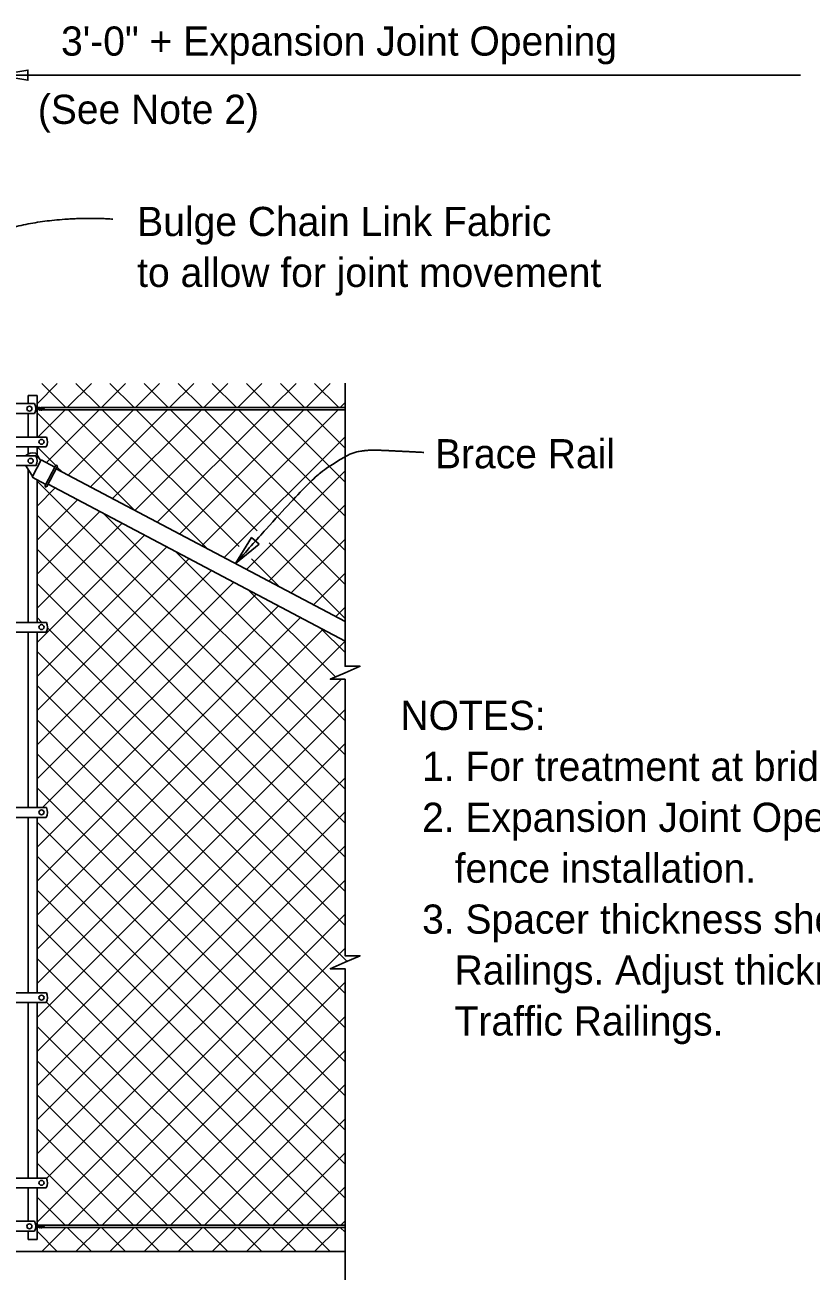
# Model space of a CAD drawing. Extents: x 0.5 to 39.7, y 0.9 to 25.6.
# Drawn here: x 28.76 to 34.2, y 17 to 25.61 of the extents above; entities that cross this region are included whole.
import ezdxf

# ---------------------------------------------------------------- set-up
doc = ezdxf.new("R2010")
doc.units = 0
for name, color, linetype in [('Dimension', 7, 'Continuous'), ('Miscellaneous', 7, 'Continuous'), ('SteelMisc', 7, 'Continuous'), ('SupstrConc', 7, 'Continuous'), ('TextStructures', 7, 'Continuous')]:
    doc.layers.add(name, color=color, linetype=linetype)

msp = doc.modelspace()

# ---------------------------------------------------------------- linework, layer by layer
at = {"layer": 'Dimension'}
msp.add_line((25.6609, 25.2672), (34.1233, 25.2672), dxfattribs=at)
for points in [[(28.5762, 25.2672), (28.7845, 25.2319), (28.7845, 25.3025)], [(30.3825, 22.0243), (30.2184, 21.8914), (30.3296, 22.071)]]:
    msp.add_lwpolyline(points, close=True, dxfattribs=at)
for points in [[(30.9762, 23.1382), (30.9762, 21.1819), (31.0795, 21.1819), (30.9762, 21.1369), (30.8729, 21.0919), (30.9762, 21.0919), (30.9762, 20.1983)], [(30.9762, 20.1983), (30.9762, 19.1806), (31.0795, 19.1806), (30.9762, 19.1356), (30.8729, 19.0906), (30.9762, 19.0906), (30.9762, 17.1361)], [(30.9761, 17.1361), (30.9761, 15.7022), (31.0795, 15.7022), (30.9761, 15.6572), (30.8728, 15.6122), (30.9761, 15.6122), (30.9761, 13.3448)]]:
    msp.add_lwpolyline(points, dxfattribs=at)
for points in [[(29.3712, 24.2725), (28.9427, 24.2977), (28.2117, 24.0791), (27.9092, 23.4903), (27.7412, 21.9834)], [(31.5199, 22.6596), (31.3633, 22.6678), (31.0749, 22.6809), (30.9256, 22.6043), (30.718, 22.4586), (30.2184, 21.8914)]]:
    msp.add_open_spline(points, degree=2, dxfattribs=at)
at = {"layer": 'Miscellaneous'}
for p, q in [((28.8471, 22.996), (28.9872, 23.1361)), ((28.8798, 23.1361), (29.0465, 22.9695)), ((29.0563, 22.9695), (29.2229, 23.1361)), ((29.1155, 23.1361), (29.2822, 22.9695)), ((29.292, 22.9695), (29.4586, 23.1361)), ((29.3512, 23.1361), (29.5179, 22.9695)), ((29.5277, 22.9695), (29.6943, 23.1361)), ((29.5869, 23.1361), (29.7536, 22.9695)), ((29.7634, 22.9695), (29.9301, 23.1361)), ((29.8226, 23.1361), (29.9893, 22.9695)), ((29.9991, 22.9695), (30.1658, 23.1361)), ((30.0583, 23.1361), (30.225, 22.9695)), ((30.2348, 22.9695), (30.4015, 23.1361)), ((30.294, 23.1361), (30.4607, 22.9695)), ((30.4705, 22.9695), (30.6372, 23.1361)), ((30.5297, 23.1361), (30.6964, 22.9695)), ((30.7062, 22.9695), (30.8729, 23.1361)), ((30.7654, 23.1361), (30.9321, 22.9695)), ((30.9419, 22.9695), (30.9762, 23.0038)), ((28.8471, 22.9331), (29.5195, 22.2607)), ((28.8522, 22.7654), (29.0415, 22.9547)), ((28.912, 22.5894), (29.2772, 22.9547)), ((29.0612, 22.9547), (30.0194, 21.9966)), ((29.0612, 22.5029), (29.5129, 22.9547)), ((29.2154, 22.4214), (29.7486, 22.9547)), ((29.2969, 22.9547), (30.2432, 22.0084)), ((29.3696, 22.3399), (29.9843, 22.9547)), ((29.5238, 22.2584), (30.22, 22.9547)), ((29.5326, 22.9547), (30.3688, 22.1185)), ((29.678, 22.177), (30.4557, 22.9547)), ((29.7683, 22.9547), (30.9762, 21.7468)), ((29.8322, 22.0955), (30.6914, 22.9547)), ((29.9864, 22.014), (30.9271, 22.9547)), ((30.004, 22.9547), (30.9762, 21.9825)), ((30.2397, 22.9547), (30.9762, 22.2182)), ((30.4754, 22.9547), (30.9762, 22.4539)), ((30.7111, 22.9547), (30.9762, 22.6896)), ((30.1406, 21.9325), (30.9762, 22.768)), ((28.8471, 22.6974), (28.9759, 22.5686)), ((28.9859, 22.5586), (29.0197, 22.5249)), ((30.2948, 21.851), (30.9762, 22.5323)), ((28.8471, 22.4617), (30.9762, 20.3326)), ((28.8471, 22.2889), (28.9724, 22.4142)), ((28.8471, 22.0532), (29.1266, 22.3327)), ((28.8471, 21.8175), (29.2808, 22.2512)), ((28.8471, 22.226), (30.9762, 20.0969)), ((29.3074, 22.2372), (30.9762, 20.5683)), ((30.449, 21.7695), (30.9762, 22.2966)), ((28.8471, 21.5818), (29.435, 22.1697)), ((28.8471, 21.3461), (29.5892, 22.0882)), ((30.6032, 21.688), (30.9762, 22.0609)), ((28.8471, 21.1104), (29.7434, 22.0067)), ((28.8471, 21.9903), (30.9762, 19.8612)), ((29.8072, 21.973), (30.9762, 20.804)), ((30.4517, 22.0356), (30.9762, 21.5111)), ((28.8471, 20.8747), (29.8977, 21.9252)), ((30.3281, 21.9235), (30.5192, 21.7324)), ((28.8471, 20.639), (30.0519, 21.8437)), ((30.7575, 21.6065), (30.9762, 21.8252)), ((28.8471, 20.4033), (30.2061, 21.7622)), ((28.8471, 21.7546), (30.9762, 19.6255)), ((30.307, 21.7089), (30.9085, 21.1074)), ((28.8897, 20.2102), (30.3603, 21.6807)), ((28.8471, 19.9319), (30.5145, 21.5993)), ((30.9117, 21.525), (30.9762, 21.5895)), ((28.8471, 21.5189), (28.8812, 21.4848)), ((28.8471, 19.6962), (30.6687, 21.5178)), ((28.8471, 19.4605), (30.8229, 21.4363)), ((28.9195, 21.4465), (30.9762, 19.3898)), ((30.8069, 21.4448), (30.9762, 21.2754)), ((28.8471, 19.2248), (30.9762, 21.3538)), ((28.8471, 21.2832), (30.9891, 19.1412)), ((28.8471, 18.9891), (30.95, 21.0919)), ((28.8471, 21.0475), (30.9762, 18.9184)), ((28.8471, 18.7534), (30.9762, 20.8824)), ((28.8471, 20.8118), (30.9762, 18.6827)), ((28.8471, 18.5177), (30.9762, 20.6467)), ((28.8471, 20.5761), (30.9762, 18.447)), ((28.8471, 18.282), (30.9762, 20.411)), ((28.8471, 20.3404), (30.9762, 18.2113)), ((28.8471, 18.0462), (30.9762, 20.1753)), ((28.8471, 20.1047), (30.9762, 17.9756)), ((28.8471, 17.8105), (30.9762, 19.9396)), ((28.8471, 19.869), (30.9762, 17.7399)), ((28.9129, 17.6406), (30.9762, 19.7039)), ((28.8471, 19.6333), (30.9762, 17.5042)), ((28.8471, 17.3391), (30.9762, 19.4682)), ((28.8471, 19.3976), (30.9271, 17.3175)), ((29.0612, 17.3175), (30.9762, 19.2325)), ((28.8471, 19.1619), (30.6914, 17.3175)), ((29.2969, 17.3175), (30.9762, 18.9968)), ((28.9129, 18.8604), (30.4557, 17.3175)), ((29.5326, 17.3175), (30.9762, 18.7611)), ((28.8471, 18.6905), (30.22, 17.3175)), ((29.7683, 17.3175), (30.9762, 18.5254)), ((28.8471, 18.4548), (29.9843, 17.3175)), ((30.004, 17.3175), (30.9762, 18.2897)), ((28.8471, 18.219), (29.7486, 17.3175)), ((30.2397, 17.3175), (30.9762, 18.054)), ((28.8471, 17.9833), (29.5129, 17.3175)), ((28.8471, 17.7476), (29.2772, 17.3175)), ((30.4754, 17.3175), (30.9762, 17.8183)), ((30.7111, 17.3175), (30.9762, 17.5826)), ((28.8471, 17.5119), (29.0415, 17.3175)), ((30.9468, 17.3175), (30.9762, 17.3469)), ((28.8471, 17.2762), (28.9872, 17.1361)), ((28.8798, 17.1361), (29.0465, 17.3028)), ((29.0563, 17.3028), (29.2229, 17.1361)), ((29.1155, 17.1361), (29.2822, 17.3028)), ((29.292, 17.3028), (29.4586, 17.1361)), ((29.3512, 17.1361), (29.5179, 17.3028)), ((29.5277, 17.3028), (29.6943, 17.1361)), ((29.5869, 17.1361), (29.7536, 17.3028)), ((29.7634, 17.3028), (29.9301, 17.1361)), ((29.8226, 17.1361), (29.9893, 17.3028)), ((29.9991, 17.3028), (30.1658, 17.1361)), ((30.0583, 17.1361), (30.225, 17.3028)), ((30.2348, 17.3028), (30.4015, 17.1361)), ((30.294, 17.1361), (30.4607, 17.3028)), ((30.4705, 17.3028), (30.6372, 17.1361)), ((30.5297, 17.1361), (30.6964, 17.3028)), ((30.7062, 17.3028), (30.8729, 17.1361)), ((30.7654, 17.1361), (30.9321, 17.3028)), ((30.9419, 17.3028), (30.9762, 17.2685))]:
    msp.add_line(p, q, dxfattribs=at)
at = {"layer": 'SteelMisc'}
for p, q in [((28.7846, 22.9966), (28.7846, 23.0528)), ((28.7846, 23.0528), (28.8471, 23.0528)), ((28.7846, 22.9966), (28.7846, 23.0528)), ((28.7846, 23.0528), (28.8471, 23.0528)), ((28.8471, 22.9726), (28.8471, 23.0528)), ((28.8471, 22.9726), (28.8471, 23.0528)), ((28.4206, 22.9966), (28.8303, 22.9966)), ((28.4206, 22.9289), (28.8299, 22.9289)), ((28.7846, 22.9288), (28.7846, 22.7653)), ((28.7846, 22.9288), (28.7846, 22.7653)), ((28.8376, 22.9741), (28.8668, 22.9695)), ((28.8377, 22.9741), (28.8669, 22.9695)), ((28.8381, 22.9537), (28.8717, 22.9593)), ((28.8382, 22.9691), (28.8642, 22.965)), ((28.8382, 22.9537), (28.8718, 22.9593)), ((28.8383, 22.9691), (28.8643, 22.965)), ((28.8385, 22.9585), (28.8684, 22.9634)), ((28.8386, 22.9585), (28.8685, 22.9634)), ((28.8471, 22.9676), (28.8471, 22.9598)), ((28.8471, 22.9676), (28.8471, 22.9598)), ((28.8471, 22.9552), (28.8471, 22.7653)), ((28.8471, 22.9552), (28.8471, 22.7653)), ((28.8842, 22.9547), (30.9762, 22.9547)), ((28.8855, 22.9695), (30.9762, 22.9695)), ((28.4206, 22.7654), (28.9116, 22.7654)), ((28.4206, 22.6977), (28.9109, 22.6977)), ((28.7846, 22.6487), (28.7846, 22.6977)), ((28.8471, 22.6411), (28.8471, 22.6977)), ((28.3139, 22.6358), (28.8387, 22.6358)), ((28.8763, 22.6083), (28.8126, 22.4877)), ((28.8728, 22.6018), (28.8381, 22.6549)), ((28.8763, 22.6083), (28.9706, 22.5585)), ((28.3139, 22.568), (28.8387, 22.568)), ((28.8168, 22.4958), (28.7699, 22.5675)), ((28.7846, 21.4848), (28.7846, 22.545)), ((28.9069, 22.4379), (28.8126, 22.4877)), ((28.9752, 22.5671), (28.9027, 22.43)), ((28.987, 22.5609), (28.9146, 22.4237)), ((30.9762, 21.4909), (28.9793, 22.5462)), ((28.8471, 21.4848), (28.8471, 22.4695)), ((30.9762, 21.3553), (28.9232, 22.4401)), ((28.4206, 21.4848), (28.9116, 21.4848)), ((28.4206, 21.4172), (28.9109, 21.4172)), ((28.7846, 20.2043), (28.7846, 21.4172)), ((28.8471, 20.2043), (28.8471, 21.4172)), ((28.4206, 20.2043), (28.9116, 20.2043)), ((28.4206, 20.1367), (28.9109, 20.1367)), ((28.7846, 18.9238), (28.7846, 20.1367)), ((28.8471, 18.9238), (28.8471, 20.1367)), ((28.9116, 18.9238), (28.2417, 18.9238)), ((28.4206, 18.8563), (28.9109, 18.8563)), ((28.7846, 17.6433), (28.7846, 18.8561)), ((28.8471, 17.6433), (28.8471, 18.8561)), ((28.4206, 17.6434), (28.9116, 17.6434)), ((28.4206, 17.5757), (28.9109, 17.5757)), ((28.7846, 17.5757), (28.7846, 17.3447)), ((28.8471, 17.3207), (28.8471, 17.5757)), ((28.3224, 17.3447), (28.8303, 17.3447)), ((28.3224, 17.3447), (28.8303, 17.3447)), ((28.8376, 17.3222), (28.8668, 17.3176)), ((28.8376, 17.3222), (28.8668, 17.3176)), ((28.8377, 17.3222), (28.8669, 17.3176)), ((28.8377, 17.3222), (28.8669, 17.3176)), ((28.8382, 17.3171), (28.8642, 17.3131)), ((28.8382, 17.3171), (28.8642, 17.3131)), ((28.8383, 17.3171), (28.8643, 17.3131)), ((28.8383, 17.3171), (28.8643, 17.3131)), ((28.8471, 17.3079), (28.8471, 17.3157)), ((28.8471, 17.3079), (28.8471, 17.3157)), ((28.8471, 17.3079), (28.8471, 17.3157)), ((28.8471, 17.3079), (28.8471, 17.3157)), ((28.8855, 17.3175), (30.9762, 17.3175)), ((28.3227, 17.2769), (28.8299, 17.2769)), ((28.3227, 17.2769), (28.8299, 17.2769)), ((28.7846, 17.2769), (28.7846, 17.2195)), ((28.8381, 17.3018), (28.8717, 17.3074)), ((28.8381, 17.3018), (28.8717, 17.3074)), ((28.8382, 17.3018), (28.8718, 17.3074)), ((28.8382, 17.3018), (28.8718, 17.3074)), ((28.8385, 17.3065), (28.8684, 17.3115)), ((28.8385, 17.3065), (28.8684, 17.3115)), ((28.8386, 17.3065), (28.8685, 17.3115)), ((28.8386, 17.3065), (28.8685, 17.3115)), ((28.8471, 17.2195), (28.8471, 17.3032)), ((28.8842, 17.3028), (30.9762, 17.3028)), ((28.7846, 17.2195), (28.8471, 17.2195))]:
    msp.add_line(p, q, dxfattribs=at)
for centre, start, end in [((28.981, 22.5639), 332.14902, 152.14902), ((28.9085, 22.4267), 152.14902, 332.14902)]:
    msp.add_arc(centre, 0.00673, start, end, dxfattribs=at)
for centre, major_axis in [((28.7943, 22.9621), (-0.0178, 0)), ((28.7943, 22.9621), (-0.0178, 0)), ((28.8779, 22.7326), (-0.0177, 0)), ((28.8779, 22.7326), (-0.0177, 0)), ((28.8028, 22.6012), (-0.0178, 0)), ((28.8779, 21.4521), (-0.0177, 0)), ((28.8779, 21.4521), (-0.0177, 0)), ((28.8779, 20.1716), (-0.0177, 0)), ((28.8779, 20.1716), (-0.0177, 0)), ((28.8779, 18.891), (-0.0177, 0)), ((28.8779, 18.891), (-0.0177, 0)), ((28.8779, 17.6106), (-0.0177, 0)), ((28.7943, 17.3102), (-0.0178, 0)), ((28.7943, 17.3102), (-0.0178, 0)), ((28.7943, 17.3102), (-0.0178, 0)), ((28.7943, 17.3102), (-0.0178, 0))]:
    msp.add_ellipse(centre, major_axis=major_axis, ratio=0.957868, dxfattribs=at)
for centre, major_axis, ratio, start_param, end_param in [((28.7609, 22.963), (0.0776, 0), 0.957868, 5.803915, 6.752041), ((28.7609, 22.963), (0.0776, 0), 0.957868, 5.803915, 6.752041), ((28.8694, 22.9596), (-0.0095, 0), 0.957868, 5.673972, 6.052579), ((28.8694, 22.9596), (-0.0095, 0), 0.957868, 5.673972, 6.052579), ((28.8694, 22.9596), (-0.0095, 0), 0.957868, 0.252467, 1.271421), ((28.8694, 22.9596), (-0.0095, 0), 0.957868, 0.252467, 1.271421), ((28.8635, 22.9555), (0.00982, 0), 0.957868, 0.655696, 1.505671), ((28.8635, 22.9555), (0.00982, 0), 0.957868, 0.655696, 1.505671), ((28.8654, 22.9604), (0.0115, -0.0041), 0.737732, 5.08821, 8.212701), ((28.8654, 22.9604), (0.0115, -0.0041), 0.737732, 5.08821, 8.212701), ((28.8688, 22.9579), (0.00301, 0), 0.957868, 3.28349, 5.170635), ((28.8688, 22.9579), (0.00301, 0), 0.957868, 3.28349, 5.170635), ((28.8695, 22.9601), (-0.00453, 0), 0.957868, 5.149727, 5.551998), ((28.8695, 22.9601), (-0.00453, 0), 0.957868, 5.149727, 5.551998), ((28.8667, 22.9588), (0.00527, 0), 0.957868, 5.058829, 7.342751), ((28.8667, 22.9588), (0.00527, 0), 0.957868, 5.058829, 7.342751), ((28.8711, 22.9612), (-0.00872, 0), 0.957868, 2.1008, 4.992926), ((28.8711, 22.9612), (-0.00872, 0), 0.957868, 2.1008, 4.992926), ((28.8688, 22.9579), (0.00301, 0), 0.957868, 0.004594, 0.141897), ((28.8688, 22.9579), (0.00301, 0), 0.957868, 0.004594, 0.141897), ((28.8772, 22.9608), (0.00944, 0), 0.957868, 4.316497, 6.557353), ((28.8772, 22.9608), (0.00944, 0), 0.957868, 4.316497, 6.557353), ((28.8776, 22.9617), (-0.00872, 0), 0.957868, 3.323334, 4.992926), ((28.8776, 22.9617), (-0.00872, 0), 0.957868, 3.323334, 4.992926), ((28.8776, 22.9617), (-0.00503, 0), 0.92697, 1.780895, 4.712389), ((28.8776, 22.9617), (-0.00503, 0), 0.92697, 1.780895, 4.712389), ((28.8824, 22.9562), (-0.0142, 0), 0.957868, 3.141593, 4.79635), ((28.8824, 22.9562), (-0.0142, 0), 0.957868, 3.141593, 4.79635), ((28.8744, 22.9412), (0.0274, 0), 0.957868, 0.628521, 1.149654), ((28.8744, 22.9412), (0.0274, 0), 0.957868, 0.628521, 1.149654), ((28.842, 22.7322), (0.0776, 0), 0.957868, 5.801244, 6.745158), ((28.842, 22.7322), (0.0776, 0), 0.957868, 5.801244, 6.745158), ((28.8215, 22.5866), (-0.0647, 0.0342), 0.957868, 4.95193, 6.011789), ((28.7695, 22.6016), (0.0776, 0), 0.957868, 5.810211, 6.75616), ((28.842, 21.4517), (0.0776, 0), 0.957868, 5.801046, 6.744962), ((28.842, 21.4517), (0.0776, 0), 0.957868, 5.801046, 6.744962), ((28.842, 20.1712), (0.0776, 0), 0.957868, 5.800848, 6.744767), ((28.842, 20.1712), (0.0776, 0), 0.957868, 5.800848, 6.744767), ((28.842, 18.8908), (0.0776, 0), 0.957868, 5.800848, 6.744767), ((28.842, 17.6101), (0.0776, 0), 0.957868, 5.800651, 6.745353), ((28.7609, 17.311), (0.0776, 0), 0.957868, 5.803915, 6.752041), ((28.7609, 17.311), (0.0776, 0), 0.957868, 5.803915, 6.752041), ((28.7609, 17.311), (0.0776, 0), 0.957868, 5.803915, 6.752041), ((28.7609, 17.311), (0.0776, 0), 0.957868, 5.803915, 6.752041), ((28.8654, 17.3084), (0.0115, -0.0041), 0.737732, 5.08821, 8.212701), ((28.8654, 17.3084), (0.0115, -0.0041), 0.737732, 5.08821, 8.212701), ((28.8654, 17.3084), (0.0115, -0.0041), 0.737732, 5.08821, 8.212701), ((28.8654, 17.3084), (0.0115, -0.0041), 0.737732, 5.08821, 8.212701), ((28.8711, 17.3093), (-0.00872, 0), 0.957868, 2.1008, 4.992926), ((28.8711, 17.3093), (-0.00872, 0), 0.957868, 2.1008, 4.992926), ((28.8711, 17.3093), (-0.00872, 0), 0.957868, 2.1008, 4.992926), ((28.8711, 17.3093), (-0.00872, 0), 0.957868, 2.1008, 4.992926), ((28.8776, 17.3098), (-0.00872, 0), 0.957868, 3.323334, 4.992926), ((28.8776, 17.3098), (-0.00872, 0), 0.957868, 3.323334, 4.992926), ((28.8776, 17.3098), (-0.00872, 0), 0.957868, 3.323334, 4.992926), ((28.8776, 17.3098), (-0.00872, 0), 0.957868, 3.323334, 4.992926), ((28.8776, 17.3098), (-0.00503, 0), 0.92697, 1.780895, 4.712389), ((28.8776, 17.3098), (-0.00503, 0), 0.92697, 1.780895, 4.712389), ((28.8776, 17.3098), (-0.00503, 0), 0.92697, 1.780895, 4.712389), ((28.8776, 17.3098), (-0.00503, 0), 0.92697, 1.780895, 4.712389), ((28.8824, 17.3043), (-0.0142, 0), 0.957868, 3.141593, 4.79635), ((28.8824, 17.3043), (-0.0142, 0), 0.957868, 3.141593, 4.79635), ((28.8824, 17.3043), (-0.0142, 0), 0.957868, 3.141593, 4.79635), ((28.8824, 17.3043), (-0.0142, 0), 0.957868, 3.141593, 4.79635), ((28.8694, 17.3077), (-0.0095, 0), 0.957868, 5.673972, 6.052579), ((28.8694, 17.3077), (-0.0095, 0), 0.957868, 5.673972, 6.052579), ((28.8694, 17.3077), (-0.0095, 0), 0.957868, 5.673972, 6.052579), ((28.8694, 17.3077), (-0.0095, 0), 0.957868, 5.673972, 6.052579), ((28.8694, 17.3077), (-0.0095, 0), 0.957868, 0.252467, 1.271421), ((28.8694, 17.3077), (-0.0095, 0), 0.957868, 0.252467, 1.271421), ((28.8694, 17.3077), (-0.0095, 0), 0.957868, 0.252467, 1.271421), ((28.8694, 17.3077), (-0.0095, 0), 0.957868, 0.252467, 1.271421), ((28.8635, 17.3035), (0.00982, 0), 0.957868, 0.655696, 1.505671), ((28.8635, 17.3035), (0.00982, 0), 0.957868, 0.655696, 1.505671), ((28.8635, 17.3035), (0.00982, 0), 0.957868, 0.655696, 1.505671), ((28.8635, 17.3035), (0.00982, 0), 0.957868, 0.655696, 1.505671), ((28.8688, 17.306), (0.00301, 0), 0.957868, 3.28349, 5.170635), ((28.8688, 17.306), (0.00301, 0), 0.957868, 3.28349, 5.170635), ((28.8688, 17.306), (0.00301, 0), 0.957868, 3.28349, 5.170635), ((28.8688, 17.306), (0.00301, 0), 0.957868, 3.28349, 5.170635), ((28.8695, 17.3082), (-0.00453, 0), 0.957868, 5.149727, 5.551998), ((28.8695, 17.3082), (-0.00453, 0), 0.957868, 5.149727, 5.551998), ((28.8695, 17.3082), (-0.00453, 0), 0.957868, 5.149727, 5.551998), ((28.8695, 17.3082), (-0.00453, 0), 0.957868, 5.149727, 5.551998), ((28.8667, 17.3069), (0.00527, 0), 0.957868, 5.058829, 7.342751), ((28.8667, 17.3069), (0.00527, 0), 0.957868, 5.058829, 7.342751), ((28.8667, 17.3069), (0.00527, 0), 0.957868, 5.058829, 7.342751), ((28.8667, 17.3069), (0.00527, 0), 0.957868, 5.058829, 7.342751), ((28.8688, 17.306), (0.00301, 0), 0.957868, 0.004594, 0.141897), ((28.8688, 17.306), (0.00301, 0), 0.957868, 0.004594, 0.141897), ((28.8688, 17.306), (0.00301, 0), 0.957868, 0.004594, 0.141897), ((28.8688, 17.306), (0.00301, 0), 0.957868, 0.004594, 0.141897), ((28.8772, 17.3089), (0.00944, 0), 0.957868, 4.316497, 6.557353), ((28.8772, 17.3089), (0.00944, 0), 0.957868, 4.316497, 6.557353), ((28.8772, 17.3089), (0.00944, 0), 0.957868, 4.316497, 6.557353), ((28.8772, 17.3089), (0.00944, 0), 0.957868, 4.316497, 6.557353), ((28.8744, 17.2893), (0.0274, 0), 0.957868, 0.628521, 1.149654), ((28.8744, 17.2893), (0.0274, 0), 0.957868, 0.628521, 1.149654), ((28.8744, 17.2893), (0.0274, 0), 0.957868, 0.628521, 1.149654), ((28.8744, 17.2893), (0.0274, 0), 0.957868, 0.628521, 1.149654)]:
    msp.add_ellipse(centre, major_axis=major_axis, ratio=ratio, start_param=start_param, end_param=end_param, dxfattribs=at)
at = {"layer": 'SupstrConc'}
msp.add_line((27.5763, 17.1361), (30.9761, 17.1361), dxfattribs=at)

# ---------------------------------------------------------------- texts
at = {"layer": 'Dimension'}
for s, p in [('Bulge Chain Link Fabric', (29.5393, 24.1553)), ('to allow for joint movement', (29.5393, 23.8033)), ('NOTES:', (31.3582, 20.7408)), ('  1. For treatment at bridge ends, see Sheet 1.', (31.3582, 20.3888)), ('  2. Expansion Joint Opening is the width at the time of', (31.3582, 20.0368)), ('     fence installation.', (31.3582, 19.6848)), ('  3. Spacer thickness shown is for Single-Slope Traffic', (31.3582, 19.3328)), ('     Railings. Adjust thickness as required for other', (31.3582, 18.9808)), ('     Traffic Railings.', (31.3582, 18.6288))]:
    msp.add_text(s, height=0.2016, dxfattribs=at).set_placement(p)
at = {"layer": 'TextStructures'}
for s, p in [('3\'-0" + Expansion Joint Opening', (29.0131, 25.4023)), ('(See Note 2)', (28.8524, 24.9306)), ('Brace Rail', (31.5972, 22.5497))]:
    msp.add_text(s, height=0.2016, dxfattribs=at).set_placement(p)

doc.saveas('drawing.dxf')
